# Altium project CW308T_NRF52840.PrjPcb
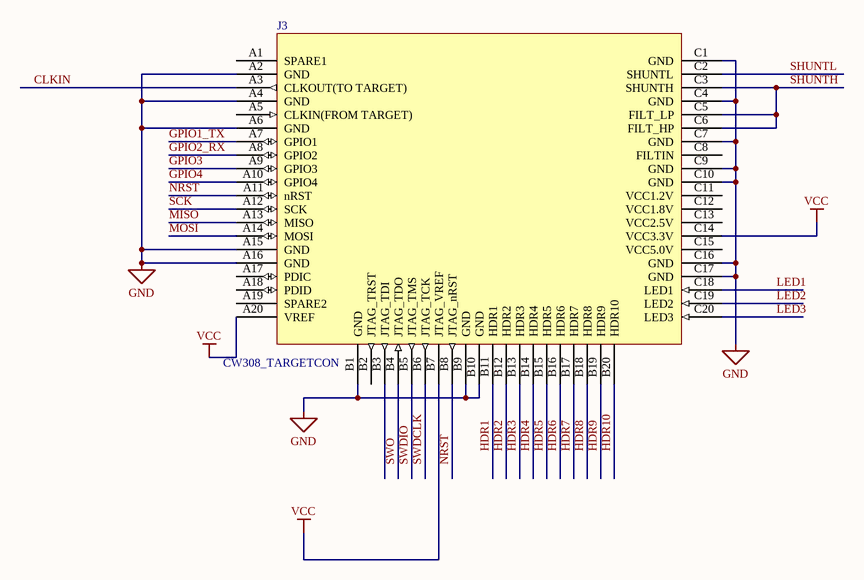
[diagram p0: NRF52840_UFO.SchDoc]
PrjRev: 00; PrjName: <Enter Project Name>; PrjLicense: <Select License>
2 sheets, 28 parts. Net scope: global (net labels, ports and power ports of the same name join across sheets).
Board file: CW308T_NRF52840.PcbDoc
Sheets:
  NRF52840_UFO.SchDoc
  NRF52840_MICRO.SchDoc

## Sheet NRF52840_UFO.SchDoc: <Enter Sheet Title>
size Letter; Organization: NewAE Technology Inc.; Address1: 1083 Queen St., Suite 196; Address2: Halifax; Address3: NS; Address4: Canada B3H 0B2; SheetApproved: NO

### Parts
(Parts that share a designator on the sheet are numbered #1, #2 ... from top to bottom, then left to right.)
J3#1  CW308_TARGETCON  [CW308_TBOARD_CONN]

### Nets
GND: J3#1.A2(GND) J3#1.A4(GND) J3#1.A6(GND) J3#1.A15(GND) J3#1.A16(GND) J3#1.B1(GND) J3#1.B9(GND) J3#1.B10(GND) J3#1.C1(GND) J3#1.C4(GND) J3#1.C7(GND) J3#1.C9(GND) J3#1.C10(GND) J3#1.C16(GND) J3#1.C17(GND)
VCC: J3#1.A20(VREF) J3#1.B7(JTAG_VREF) J3#1.C14(VCC3.3V)
CLKIN: J3#1.A3(CLKOUT(TO_TARGET))
GPIO1_TX: J3#1.A7(GPIO1)
GPIO2_RX: J3#1.A8(GPIO2)
GPIO3: J3#1.A9(GPIO3)
GPIO4: J3#1.A10(GPIO4)
HDR1: J3#1.B11(HDR1)
HDR2: J3#1.B12(HDR2)
HDR3: J3#1.B13(HDR3)
HDR4: J3#1.B14(HDR4)
HDR5: J3#1.B15(HDR5)
HDR6: J3#1.B16(HDR6)
HDR7: J3#1.B17(HDR7)
HDR8: J3#1.B18(HDR8)
HDR9: J3#1.B19(HDR9)
HDR10: J3#1.B20(HDR10)
LED1: J3#1.C18(LED1)
LED2: J3#1.C19(LED2)
LED3: J3#1.C20(LED3)
MISO: J3#1.A13(MISO)
MOSI: J3#1.A14(MOSI)
NRST: J3#1.A11(nRST) J3#1.B8(JTAG_nRST)
SCK: J3#1.A12(SCK)
SHUNTH: J3#1.C3(SHUNTH) J3#1.C5(FILT_LP) J3#1.C6(FILT_HP)
SHUNTL: J3#1.C2(SHUNTL)
SWDCLK: J3#1.B6(JTAG_TCK)
SWDIO: J3#1.B5(JTAG_TMS)
SWO: J3#1.B4(JTAG_TDO)

Not connected (* = marked no-connect by the designer): J3#1 A1(SPARE1) A5(CLKIN(FROM_TARGET)) A17(PDIC) A18(PDID) A19(SPARE2) B2(JTAG_TRST) B3(JTAG_TDI) C8(FILTIN) C11(VCC1.2V) C12(VCC1.8V) C13(VCC2.5V) C15(VCC5.0V)

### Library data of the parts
J3#1 = CW308_TBOARD: CW308 "Standard" Target Board Connector; Component Group: Mechanical; Pitch: 2.54mm

## Sheet NRF52840_MICRO.SchDoc: <Enter Sheet Title>
size Letter; Organization: NewAE Technology Inc.; Address1: 1083 Queen St., Suite 196; Address2: Halifax; Address3: NS; Address4: Canada B3H 0B2; SheetApproved: NO
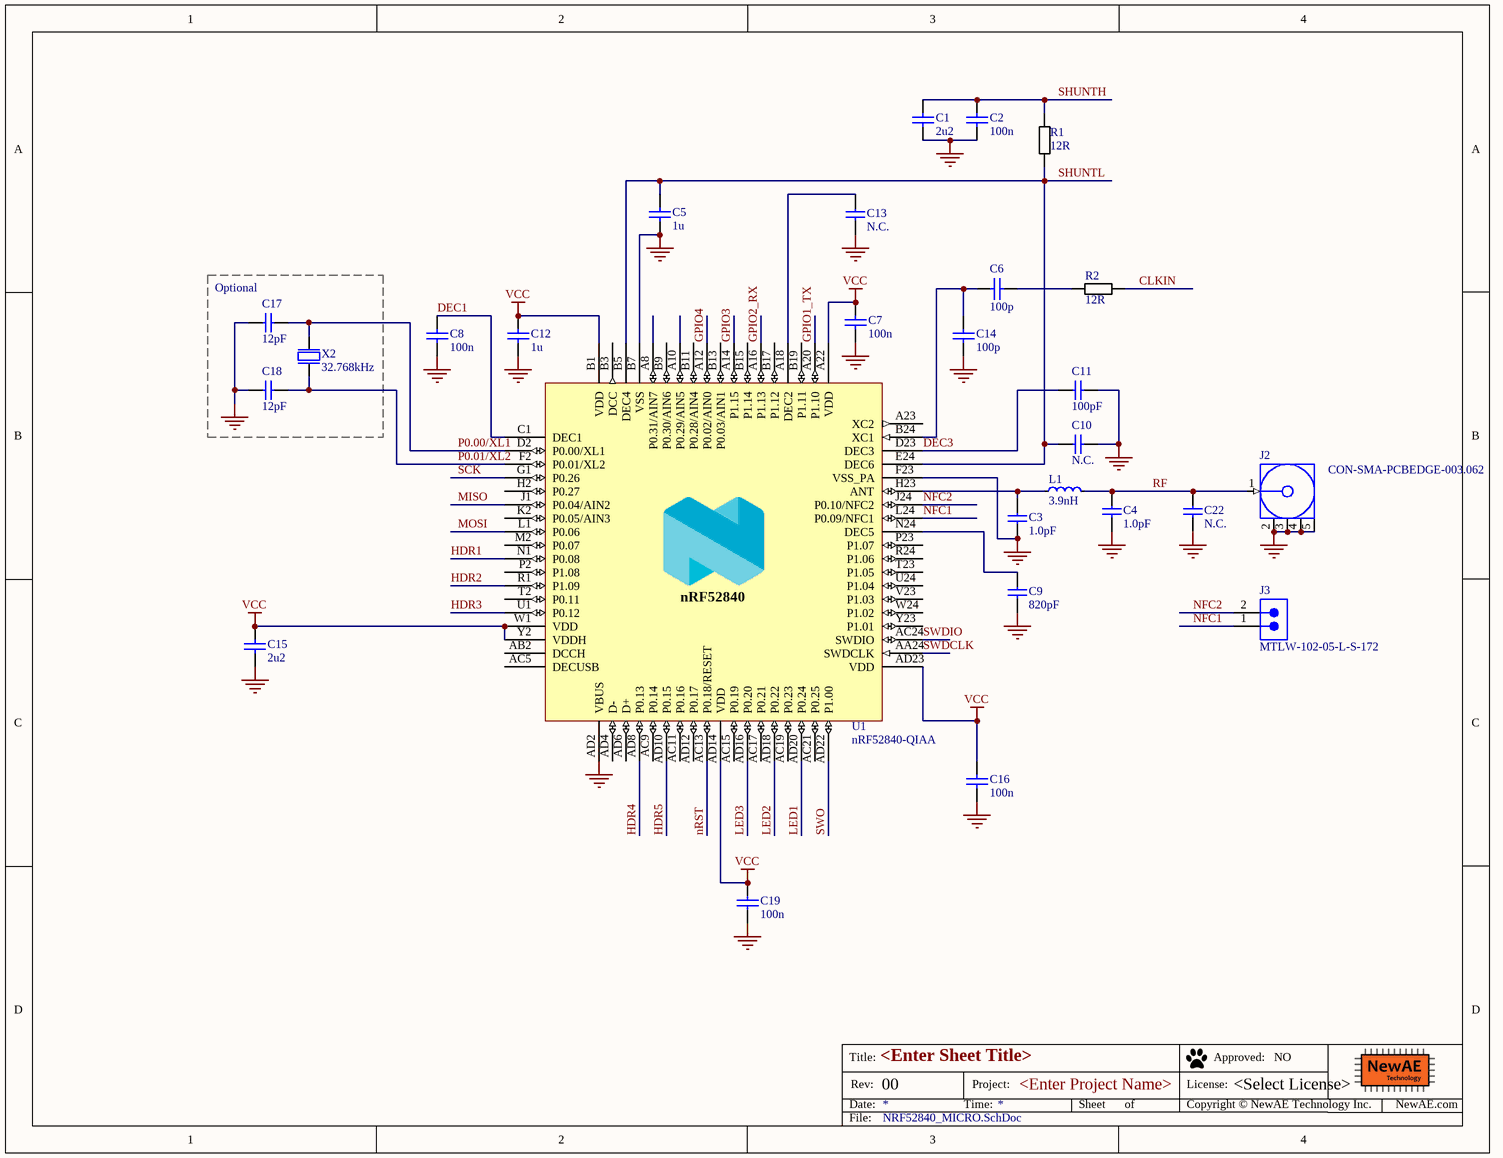
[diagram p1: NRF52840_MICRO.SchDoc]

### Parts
(Parts that share a designator on the sheet are numbered #1, #2 ... from top to bottom, then left to right.)
C1  2u2  [CAPC0603_M]
C2  100n  [CAPC0603_M]
C3  1.0pF  [CAPC1005X04L]
C4  1.0pF  [CAPC1005X04L]
C5  1u  [CAPC0603_M]
C6  100p  [CAPC0603_M]
C7  100n  [CAPC0603_M]
C8  100n  [CAPC0603_M]
C9  820pF  [CAPC1005X04L]
C10  N.C.  [CAPC1005X04L]
C11  100pF  [CAPC1005X04L]
C12  1u  [CAPC0603_M]
C13  N.C.  [CAPC1005X04L]
C14  100p  [CAPC0603_M]
C15  2u2  [CAPC0603_M]
C16  100n  [CAPC0603_M]
C17  12pF  [CAPC1005X04L]
C18  12pF  [CAPC1005X04L]
C19  100n  [CAPC0603_M]
C22  N.C.  [CAPC1005X04L]
J2  CON-SMA-PCBEDGE-003.062  [CON-SMAM-PCB-EDGE062]
J3#2  MTLW-102-05-L-S-172  [SMTC-MTLW-102-05-X-S-172]
L1  3.9nH  [INDC1005X04L]
R1  12R  [RESC1608X55N]
R2  12R  [RESC1608X55N]
U1  nRF52840-QIAA  [AQFN50P700X700X85_HS-74N]
X2  32.768kHz  [XTAL_3215]

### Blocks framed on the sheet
Optional: C17 C18 X2

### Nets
GND: C1.2 C2.2 C3.1 C4.1 C5.2 C7.2 C8.2 C9.2 C10.1 C11.2 C12.2 C13.2 C14.2 C15.2 C16.2 C17.2 C18.2 C19.2 C22.2 J2.2(GND) J2.3(GND) J2.4(GND) J2.5(GND) U1.74(GND) U1.AD2(VBUS) U1.B7(VSS) U1.F23(VSS_PA)
VCC: C7.1 C12.1 C15.1 C16.1 C19.1 U1.A22(VDD) U1.AD14(VDD) U1.AD23(VDD) U1.B1(VDD) U1.W1(VDD) U1.Y2(VDDH)
CLKIN: R2.2
DEC1: C8.1 U1.C1(DEC1)
DEC3: C11.1 U1.D23(DEC3)
GPIO1_TX: U1.A20(P1.10)
GPIO2_RX: U1.A16(P1.13)
GPIO3: U1.A14(P1.15)
GPIO4: U1.A12(P0.02/AIN0)
HDR1: U1.N1(P0.08)
HDR2: U1.R1(P1.09)
HDR3: U1.U1(P0.12)
HDR4: U1.AD8(P0.13)
HDR5: U1.AD10(P0.15)
LED1: U1.AD20(P0.24)
LED2: U1.AD18(P0.22)
LED3: U1.AD16(P0.20)
MISO: U1.J1(P0.04/AIN2)
MOSI: U1.L1(P0.06)
NFC1: J3#2.1 U1.L24(P0.09/NFC1)
NFC2: J3#2.2 U1.J24(P0.10/NFC2)
NRST: U1.AC13(P0.18/RESET)
P0.00/XL1: C17.1 U1.D2(P0.00/XL1) X2.1(inp)
P0.01/XL2: C18.1 U1.F2(P0.01/XL2) X2.2(out)
RF: C4.2 C22.1 J2.1(Signal) L1.2
SCK: U1.G1(P0.26)
SHUNTH: C1.1 C2.1 R1.1
SHUNTL: C5.1 C10.2 R1.2 U1.B5(DEC4) U1.E24(DEC6)
SWDCLK: U1.AA24(SWDCLK)
SWDIO: U1.AC24(SWDIO)
SWO: U1.AD22(P1.00)
NetC3_2: C3.2 L1.1 U1.H23(ANT)
NetC6_1: C6.1 C14.1 U1.B24(XC1)
NetC6_2: C6.2 R2.1
NetC9_1: C9.1 U1.N24(DEC5)
NetC13_1: C13.1 U1.A18(DEC2)

Not connected (* = marked no-connect by the designer): U1 A8(P0.31/AIN7) A10(P0.29/AIN5) A23(XC2) AB2(DCCH) AC5(DECUSB) AC9(P0.14) AC11(P0.16) AC15(P0.19) AC17(P0.21) AC19(P0.23) AC21(P0.25) AD4(D-) AD6(D+) AD12(P0.17) B3(DCC) B9(P0.30/AIN6) B11(P0.28/AIN4) B13(P0.03/AIN1) B15(P1.14) B17(P1.12) B19(P1.11) H2(P0.27) K2(P0.05/AIN3) M2(P0.07) P2(P1.08) P23(P1.07) R24(P1.06) T2(P0.11) T23(P1.05) U24(P1.04) V23(P1.03) W24(P1.02) Y23(P1.01)

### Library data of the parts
C1 C15 = CCHIP-2u2-0603: 2u2, 0603; Manufacture 1: Samsung; Manufacture Part Number 1: CL10B225KP8NNNC; Component Group: Capacitor; Case-EIA: 0603; Case-Metric: 1608; Rated Voltage: 10VDC
C2 C7 C8 C16 C19 = CCHIP-100n-0603: 100n, 0603; Manufacture 1: Kemet; Manufacture Part Number 1: C0603C104K5RACTU; Component Group: Capacitor; Case-EIA: 0603; Case-Metric: 1608; Rated Voltage: 50VDC
C3 C4 = C0402-1.0p: Capacitor, NP0, ±5%; Note: 50V
C5 C12 = CCHIP-1u-0603: 1u, 0603, 50V; Manufacture Part Number 1: CL10A105KB8NNNC; Component Group: Capacitor; Case-EIA: 0603; Case-Metric: 1608; Rated Voltage: 50VDC
C6 C14 = CCHIP-100p-0603: 100p, 0603; Manufacture 1: KEMET; Manufacture Part Number 1: C0603C101K5RACTU; Component Group: Capacitor; Case-EIA: 0603; Case-Metric: 1608; Rated Voltage: 50V
C9 = C0402-820p: Capacitor, NP0, ±5%; Note: 50V
C10 C13 = C0402-N.C.: Not mounted; Assembly: Not mounted
C11 = C0402-100p: Capacitor, NP0, ±5%; Note: 50V
C17 C18 = C0402-12p: Capacitor, NP0, ±2%; Note: 50V
C22 = C0402-N.C.: Not mounted; Note: Chip Cap; Assembly: Not mounted
J2 = CON-SMA-PCBEDGE-003.062: SMA Female Edge Mount Connector for 0.062" Thick Board; PCB_Layout: Pads complies with manufacturer's recommendation.
J3#2 = CMP-1024-00067-1: Manufacturer: Samtec; Pitch: 2.54 mm
L1 = L0402-3n9: High frequency chip inductor ±5%
R1 R2 = RCHIP-12R-0603: 12R res, 0603, 1%, 1/10W; Manufacture 1: Yageo; Manufacture Part Number 1: RC0603FR-0712RL; Component Group: Resistor; Case-EIA: 0603; Case-Metric: 1608; Rated Power: 0.1W; Rated Voltage: 75VDC
U1 = nRF52840-QIAAC0: Multi-protocol Bluetooth Low Energy, IEEE 802.15.4, ANT and 2.4GHz proprietary system-on-chip; Manufacturer: Nordic Semiconductor
X2 = XTAL_SMD3215_32.768kHz_9pF_General: XTAL SMD 3215, 32.768kHz, Cl=9pF, Total Tol: ±50ppm

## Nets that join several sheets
GND: NRF52840_UFO (15 pins), NRF52840_MICRO (27 pins)
VCC: NRF52840_UFO (J3#1.A20 J3#1.B7 J3#1.C14), NRF52840_MICRO (11 pins)
CLKIN: NRF52840_UFO (J3#1.A3), NRF52840_MICRO (R2.2)
GPIO1_TX: NRF52840_UFO (J3#1.A7), NRF52840_MICRO (U1.A20)
GPIO2_RX: NRF52840_UFO (J3#1.A8), NRF52840_MICRO (U1.A16)
GPIO3: NRF52840_UFO (J3#1.A9), NRF52840_MICRO (U1.A14)
GPIO4: NRF52840_UFO (J3#1.A10), NRF52840_MICRO (U1.A12)
HDR1: NRF52840_UFO (J3#1.B11), NRF52840_MICRO (U1.N1)
HDR2: NRF52840_UFO (J3#1.B12), NRF52840_MICRO (U1.R1)
HDR3: NRF52840_UFO (J3#1.B13), NRF52840_MICRO (U1.U1)
HDR4: NRF52840_UFO (J3#1.B14), NRF52840_MICRO (U1.AD8)
HDR5: NRF52840_UFO (J3#1.B15), NRF52840_MICRO (U1.AD10)
LED1: NRF52840_UFO (J3#1.C18), NRF52840_MICRO (U1.AD20)
LED2: NRF52840_UFO (J3#1.C19), NRF52840_MICRO (U1.AD18)
LED3: NRF52840_UFO (J3#1.C20), NRF52840_MICRO (U1.AD16)
MISO: NRF52840_UFO (J3#1.A13), NRF52840_MICRO (U1.J1)
MOSI: NRF52840_UFO (J3#1.A14), NRF52840_MICRO (U1.L1)
NRST: NRF52840_UFO (J3#1.A11 J3#1.B8), NRF52840_MICRO (U1.AC13)
SCK: NRF52840_UFO (J3#1.A12), NRF52840_MICRO (U1.G1)
SHUNTH: NRF52840_UFO (J3#1.C3 J3#1.C5 J3#1.C6), NRF52840_MICRO (C1.1 C2.1 R1.1)
SHUNTL: NRF52840_UFO (J3#1.C2), NRF52840_MICRO (5 pins)
SWDCLK: NRF52840_UFO (J3#1.B6), NRF52840_MICRO (U1.AA24)
SWDIO: NRF52840_UFO (J3#1.B5), NRF52840_MICRO (U1.AC24)
SWO: NRF52840_UFO (J3#1.B4), NRF52840_MICRO (U1.AD22)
